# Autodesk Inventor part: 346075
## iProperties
Company: Mayer & Müller AG Schaltgeräte
Created: 2005-10
Part Number: 346075
Material: Roccasol 200
Document SubType Name: Modeling
Designer: I.Baliuc
Manufacturer: Standard
Standards Organization: Custom
Description: Isolator
Density: 1.14 g/cm^3
Author: T.Messerschmitt
Comments: Isoliermasse Roccasol 200 Fa.Irle u. heuel temper. +160°C
Revision Number: 346240
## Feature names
1. Extrusion2
2. Bohrung1 [Hole]
3. Drehung1 [Revolution]
4. Rechteckige Anordnung1 [Rectangular Pattern]
5. Bohrung2 [Hole]
6. Drehung2 [Revolution]
7. Rechteckige Anordnung2 [Rectangular Pattern]
